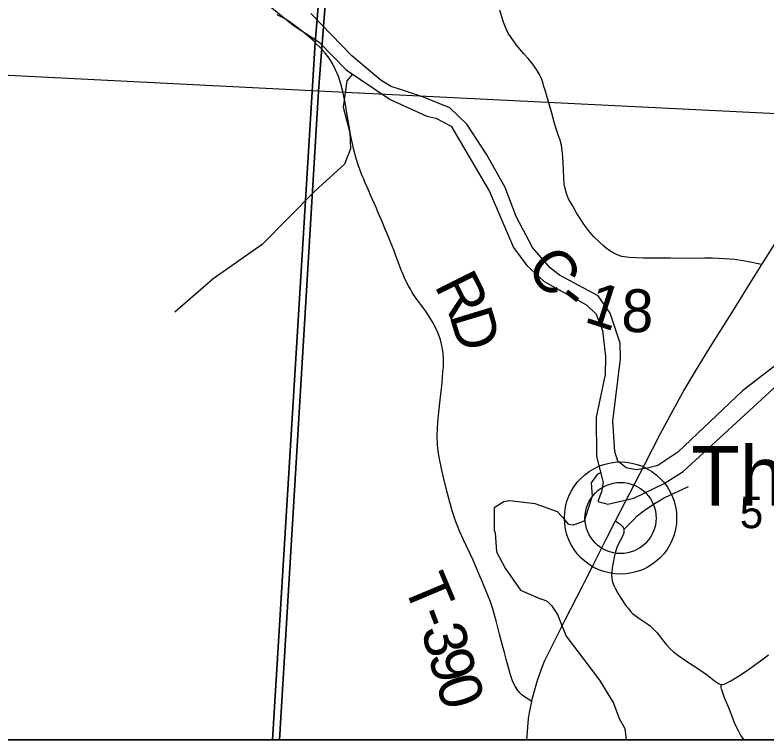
# Model space of a CAD drawing. Extents: x 0 to 34, y 0 to 22.
# Drawn here: x 25.892 to 26.889, y 14.1 to 15.061 of the extents above; entities that cross this region are included whole.
import ezdxf

# ---------------------------------------------------------------- set-up
doc = ezdxf.new("R2010")
doc.units = 0
for name, color, linetype in [('Default', 7, 'Continuous'), ('GM_X_County_Road', 7, 'Continuous'), ('GM_X_County_Road_Text', 7, 'Continuous'), ('GM_X_Major_River', 7, 'Continuous'), ('GM_X_Minor_River', 7, 'Continuous'), ('GM_X_Section', 7, 'Continuous'), ('GM_X_Section_Text', 7, 'Continuous'), ('GM_X_State_Route', 7, 'Continuous'), ('GM_X_Township_Road', 7, 'Continuous'), ('GM_X_Township_Road_Text', 7, 'Continuous'), ('GM_X_Unincorporated', 7, 'Continuous'), ('GM_X_Unincorporated_Location', 7, 'Continuous'), ('GM_X_Unincorporated_Text', 7, 'Continuous'), ('SH_Data', 7, 'Continuous'), ('SH_Text', 7, 'Continuous')]:
    doc.layers.add(name, color=color, linetype=linetype)

msp = doc.modelspace()

# ---------------------------------------------------------------- linework, layer by layer
at = {"layer": 'Default'}
for points in [[(23.51667, 16.12386), (23.51667, 14.1), (26.23309, 14.1), (26.29003, 15.02462), (26.31534, 15.32786), (26.36245, 15.9099), (26.36913, 15.98287), (26.08107, 15.99207), (25.34583, 16.01913), (25.05347, 16.03312), (23.58881, 16.11946)], [(25.19744, 14.1), (26.24241, 14.1), (26.29435, 14.96008), (25.25344, 15.01279)], [(26.24241, 14.1), (27.30639, 14.1), (27.31016, 14.15895), (27.32664, 14.41829), (27.34196, 14.6691), (27.35718, 14.9074), (26.29435, 14.96008)]]:
    msp.add_lwpolyline(points, close=True, dxfattribs=at)
msp.add_lwpolyline([(26.89534, 15.95367), (26.88657, 15.95357), (26.87728, 15.95301), (26.36913, 15.98287), (26.36245, 15.9099), (26.31534, 15.32786), (26.29003, 15.02462), (26.23309, 14.1), (29.50513, 14.1)], dxfattribs=at)
at = {"layer": 'GM_X_County_Road'}
for points in [[(26.88229, 14.73025), (26.87951, 14.73084), (26.86652, 14.73359), (26.85736, 14.73528), (26.84628, 14.73686), (26.83914, 14.73744), (26.83201, 14.73802), (26.82461, 14.73828), (26.81645, 14.73857), (26.8065, 14.73862), (26.78479, 14.73832), (26.76087, 14.73879), (26.74168, 14.73867), (26.72529, 14.73873), (26.71601, 14.73921), (26.70621, 14.73955), (26.69663, 14.74094), (26.69044, 14.74296), (26.68485, 14.74585), (26.68062, 14.74833), (26.67572, 14.75206), (26.67199, 14.75527), (26.66576, 14.7608), (26.65905, 14.76763), (26.65242, 14.77532), (26.6484, 14.78062), (26.64526, 14.78515), (26.64118, 14.79134), (26.63682, 14.79814), (26.63099, 14.80834), (26.62595, 14.81755), (26.62318, 14.82445), (26.62125, 14.83094), (26.62012, 14.83697), (26.6194, 14.84555), (26.61866, 14.86519), (26.61834, 14.87261), (26.61747, 14.8819), (26.61625, 14.88865), (26.61405, 14.89642), (26.61246, 14.90109), (26.60916, 14.91133), (26.60688, 14.91915), (26.6036, 14.93077), (26.59969, 14.94452), (26.59567, 14.95835), (26.59482, 14.96135), (26.59325, 14.96653), (26.59211, 14.97027), (26.58983, 14.97675), (26.58722, 14.98243), (26.58341, 14.98883), (26.57803, 14.99638), (26.57209, 15.0035), (26.56673, 15.00948), (26.56387, 15.01273), (26.55912, 15.0184), (26.5572, 15.02079), (26.55272, 15.02681), (26.54952, 15.03112), (26.54595, 15.03689), (26.54289, 15.04293), (26.53948, 15.05155), (26.53719, 15.0586), (26.53477, 15.06757)], [(26.68814, 14.39031), (26.69215, 14.38758), (26.69394, 14.38635), (26.69557, 14.38494), (26.6971, 14.38342), (26.69824, 14.38177), (26.69875, 14.38061), (26.6992, 14.37917), (26.69931, 14.37759), (26.6992, 14.37616), (26.69899, 14.37463), (26.69863, 14.37319), (26.69727, 14.36981), (26.69478, 14.36505), (26.69223, 14.35996), (26.69002, 14.35494), (26.68813, 14.34927), (26.6864, 14.34245), (26.68492, 14.33522), (26.68368, 14.32806), (26.68312, 14.32283), (26.68285, 14.3183), (26.68312, 14.31433), (26.68377, 14.31081), (26.68497, 14.30711), (26.68636, 14.30369), (26.68802, 14.30018), (26.69125, 14.29454), (26.69544, 14.28771), (26.70061, 14.28008), (26.70283, 14.27711), (26.70431, 14.27515), (26.7062, 14.27275), (26.70902, 14.26953), (26.71076, 14.26785), (26.71358, 14.2655), (26.71703, 14.26288), (26.71901, 14.26148), (26.72975, 14.25436), (26.73225, 14.25257), (26.73415, 14.25111), (26.73552, 14.2499), (26.73946, 14.24605), (26.74317, 14.24192), (26.75039, 14.23265), (26.75584, 14.22594), (26.7604, 14.22095), (26.76487, 14.21673), (26.77091, 14.21225), (26.7821, 14.20461), (26.79236, 14.198), (26.80268, 14.19101), (26.80429, 14.18987)], [(26.82774, 14.17352), (26.83012, 14.17362), (26.83245, 14.17411), (26.83655, 14.17599), (26.84088, 14.17833), (26.85115, 14.18471), (26.86247, 14.19223), (26.87423, 14.20056), (26.88019, 14.20498), (26.88564, 14.20899), (26.89103, 14.21305)], [(26.80429, 14.18987), (26.8099, 14.18584), (26.81952, 14.17833), (26.82339, 14.17554), (26.82572, 14.17422), (26.82774, 14.17352)], [(26.85848, 14.1), (26.85429, 14.10601), (26.85101, 14.11195), (26.848, 14.11787), (26.84499, 14.12486), (26.84225, 14.13239), (26.83832, 14.14258), (26.83278, 14.15594), (26.82861, 14.16797), (26.82823, 14.16935), (26.82798, 14.17075), (26.82774, 14.17352)]]:
    msp.add_lwpolyline(points, dxfattribs=at)
at = {"layer": 'GM_X_Major_River'}
for points in [[(26.2252, 15.07622), (26.26046, 15.04751), (26.29534, 15.02525), (26.331, 14.98857), (26.38937, 14.94893), (26.43787, 14.92708), (26.45003, 14.92418)], [(26.43354, 14.95235), (26.4041, 14.96186), (26.39047, 14.96637), (26.3772, 14.9743), (26.33852, 15.00717), (26.28428, 15.06312)], [(26.90627, 14.60123), (26.85655, 14.563), (26.77076, 14.48169), (26.74401, 14.4637), (26.73041, 14.46021), (26.71529, 14.45822), (26.70242, 14.4608), (26.69103, 14.46946), (26.68718, 14.48233), (26.68469, 14.52253), (26.69483, 14.60529), (26.69434, 14.62616), (26.68088, 14.66591), (26.66488, 14.68896), (26.61367, 14.71635), (26.60152, 14.72576), (26.57792, 14.75294), (26.55614, 14.79378), (26.54156, 14.83239), (26.5175, 14.87588), (26.4908, 14.91631), (26.46844, 14.93812), (26.43354, 14.95235)], [(26.45003, 14.92418), (26.47002, 14.91353), (26.52117, 14.82696), (26.55296, 14.75279), (26.57049, 14.729), (26.59329, 14.70789), (26.65019, 14.67635), (26.66236, 14.66466), (26.6708, 14.64271), (26.67477, 14.60859), (26.67452, 14.58431), (26.66235, 14.52809), (26.66301, 14.47574), (26.67189, 14.44127), (26.66969, 14.42874), (26.66447, 14.41619), (26.6781, 14.41248), (26.71247, 14.42065), (26.75246, 14.43985), (26.77771, 14.45593), (26.82663, 14.50061), (26.93125, 14.59682)]]:
    msp.add_lwpolyline(points, dxfattribs=at)
at = {"layer": 'GM_X_Minor_River'}
for points in [[(26.33924, 14.98286), (26.33181, 14.97367), (26.32709, 14.93871), (26.33564, 14.90534), (26.33654, 14.8837), (26.32869, 14.86354), (26.28944, 14.82764), (26.21966, 14.75703), (26.15467, 14.71151), (26.1037, 14.66721)], [(26.66838, 14.45411), (26.66375, 14.45195), (26.65583, 14.44091), (26.65698, 14.42305), (26.6517, 14.40669), (26.64642, 14.38996), (26.63206, 14.3846), (26.62639, 14.38573), (26.62147, 14.39142), (26.61125, 14.40242), (26.58176, 14.41299), (26.54773, 14.4171), (26.54017, 14.41556), (26.52733, 14.40793), (26.52736, 14.37828), (26.52849, 14.37448), (26.53041, 14.3494), (26.54177, 14.32776), (26.56221, 14.29854), (26.58971, 14.2868)], [(26.58946, 14.28689), (26.59738, 14.28418), (26.60306, 14.2781), (26.61138, 14.26634), (26.62275, 14.23748), (26.66666, 14.17905), (26.68559, 14.14868), (26.69279, 14.12855), (26.70036, 14.11527), (26.7022, 14.1)]]:
    msp.add_lwpolyline(points, dxfattribs=at)
at = {"layer": 'GM_X_Section'}
for points in [[(25.30908, 16.0203), (26.36132, 15.98463), (26.37345, 15.98428), (26.29435, 14.96008), (25.25344, 15.01279)], [(26.37345, 15.98428), (27.4216, 15.93275), (27.40988, 15.69364), (27.39203, 15.43909), (27.37534, 15.17868), (27.35741, 14.91067), (27.35718, 14.9074), (26.29435, 14.96008)]]:
    msp.add_lwpolyline(points, close=True, dxfattribs=at)
at = {"layer": 'GM_X_State_Route'}
for points in [[(26.88229, 14.73025), (26.90971, 14.77385)], [(26.60974, 14.23622), (26.61111, 14.23898), (26.62048, 14.25758), (26.63678, 14.28933), (26.64416, 14.30386), (26.64677, 14.309), (26.658, 14.33083), (26.67545, 14.36527), (26.68814, 14.39031), (26.72647, 14.46473), (26.74796, 14.50608), (26.7617, 14.53253), (26.77774, 14.56156), (26.79265, 14.58685), (26.8134, 14.62074), (26.84438, 14.66985), (26.86672, 14.70551), (26.88229, 14.73025)], [(26.58852, 14.1902), (26.5895, 14.19303), (26.59414, 14.2045), (26.60104, 14.21869), (26.60974, 14.23622)], [(26.57731, 14.15213), (26.58064, 14.1653), (26.58527, 14.18074), (26.58852, 14.1902)], [(26.57046, 14.1), (26.57084, 14.10525), (26.57279, 14.12839), (26.57403, 14.13633), (26.57707, 14.15118), (26.57731, 14.15213)]]:
    msp.add_lwpolyline(points, dxfattribs=at)
at = {"layer": 'GM_X_Township_Road'}
for points in [[(26.29092, 15.02342), (26.29024, 15.0241), (26.28668, 15.02765), (26.27702, 15.03601), (26.26558, 15.04516), (26.25661, 15.05175), (26.24843, 15.05694), (26.23946, 15.06151)], [(26.57707, 14.15118), (26.57222, 14.15388), (26.56729, 14.15696), (26.56426, 14.15926), (26.56116, 14.1624), (26.55773, 14.16692), (26.55492, 14.17132), (26.55193, 14.17722), (26.54877, 14.18645), (26.54327, 14.20729), (26.54083, 14.21599), (26.53823, 14.22525), (26.53428, 14.24026), (26.5319, 14.24929), (26.52965, 14.2581), (26.5273, 14.26733), (26.52534, 14.27386), (26.52211, 14.28323), (26.5183, 14.29306), (26.51173, 14.30916), (26.50745, 14.31948), (26.50297, 14.32975), (26.49926, 14.33825), (26.49559, 14.34605), (26.49052, 14.3568), (26.48667, 14.3653), (26.48178, 14.37605), (26.47861, 14.38404), (26.47651, 14.38936), (26.47429, 14.39577), (26.47203, 14.40229), (26.46863, 14.4136), (26.46365, 14.43349), (26.46043, 14.44613), (26.45721, 14.46006), (26.45465, 14.47287), (26.45303, 14.4827), (26.45212, 14.49201), (26.45181, 14.50198), (26.45218, 14.51443), (26.45301, 14.52622), (26.45423, 14.53859), (26.45522, 14.54712), (26.45652, 14.55834), (26.45767, 14.56947), (26.45811, 14.57413), (26.45873, 14.5806), (26.45926, 14.58739), (26.45984, 14.59482), (26.46005, 14.60533), (26.4596, 14.61273), (26.45845, 14.62067), (26.45614, 14.63028), (26.45355, 14.63787), (26.45032, 14.64523), (26.44602, 14.65344), (26.44119, 14.66138), (26.43686, 14.66754), (26.43371, 14.67202), (26.42368, 14.68548), (26.41853, 14.69327), (26.41607, 14.69754), (26.41355, 14.70192), (26.4088, 14.71139), (26.40639, 14.71725), (26.40453, 14.72175), (26.39639, 14.74323), (26.3944, 14.74845), (26.39239, 14.75366), (26.38848, 14.76346), (26.38395, 14.77433), (26.38323, 14.77604), (26.37814, 14.78805), (26.3752, 14.79489), (26.37297, 14.80002), (26.37052, 14.80572), (26.36831, 14.81086), (26.36337, 14.82224), (26.36081, 14.82789), (26.35859, 14.833), (26.35591, 14.83928), (26.35422, 14.84328), (26.35228, 14.84785), (26.34953, 14.85505), (26.34673, 14.86239), (26.34407, 14.87069), (26.3412, 14.88216), (26.33686, 14.90286), (26.33575, 14.90833), (26.33228, 14.92854), (26.32952, 14.94508), (26.32653, 14.95949), (26.32389, 14.9697), (26.32062, 14.97976), (26.31685, 14.9886), (26.31289, 14.99661), (26.30841, 15.00382), (26.30322, 15.01041), (26.29636, 15.01798), (26.29092, 15.02342)], [(26.6992, 14.37917), (26.703, 14.38279), (26.71178, 14.39193), (26.71691, 14.397), (26.72258, 14.40163), (26.7286, 14.40601), (26.73848, 14.41248), (26.74807, 14.41824), (26.75185, 14.42038), (26.76189, 14.42531), (26.7715, 14.42971), (26.78491, 14.43624)]]:
    msp.add_lwpolyline(points, dxfattribs=at)
at = {"layer": 'GM_X_Unincorporated'}
for radius in [0.0744, 0.04716]:
    msp.add_circle((26.69474, 14.39424), radius, dxfattribs=at)
at = {"layer": 'GM_X_Unincorporated_Location'}
msp.add_line((26.69474, 14.39424), (26.69474, 14.39424), dxfattribs=at)
at = {"layer": 'SH_Data'}
msp.add_lwpolyline([(23.51667, 20.9), (30.31667, 20.9), (30.31667, 14.1), (23.51667, 14.1)], close=True, dxfattribs=at)
at = {"layer": 'SH_Text'}
msp.add_lwpolyline([(30.31667, 20.9), (23.51667, 20.9), (23.51667, 14.1), (29.50513, 14.1)], dxfattribs=at)

# ---------------------------------------------------------------- texts
at = {"layer": 'GM_X_County_Road_Text'}
for s, rotation, p in [('C', 309.08771, (26.5677, 14.72535)), ('-', 322.13978, (26.60721, 14.67926)), ('1', 342.33024, (26.64488, 14.6548)), ('8', 358.41684, (26.69535, 14.64127))]:
    msp.add_text(s, height=0.05682, rotation=rotation, dxfattribs=at).set_placement(p)
at = {"layer": 'GM_X_Section_Text'}
msp.add_text('5', height=0.04186, rotation=0.00001, dxfattribs=at).set_placement((26.85289, 14.38075))
at = {"layer": 'GM_X_Township_Road_Text'}
for s, rotation, p in [('R', 296.64273, (26.44734, 14.70247)), ('D', 286.93669, (26.46733, 14.66312)), ('T', 292.75404, (26.40606, 14.30576)), ('-', 290.72004, (26.4223, 14.26706)), ('3', 284.9968, (26.4301, 14.24666)), ('9', 285.59666, (26.43933, 14.21223)), ('0', 287.34397, (26.44927, 14.17671))]:
    msp.add_text(s, height=0.05682, rotation=rotation, dxfattribs=at).set_placement(p)
at = {"layer": 'GM_X_Unincorporated_Text'}
msp.add_text('Thivener', height=0.078977, rotation=0.00001, dxfattribs=at).set_placement((26.78831, 14.41054))

doc.saveas('drawing.dxf')
